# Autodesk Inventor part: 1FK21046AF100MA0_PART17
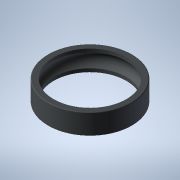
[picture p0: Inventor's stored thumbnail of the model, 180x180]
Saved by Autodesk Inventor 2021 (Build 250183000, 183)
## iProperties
Created: 2025-04
Part Number: 1FK21046AF100MA0_PART17
Material: Generic
Catalog Web Link: www.3dfindit.com
Description: -Servo synchronous motor
Document SubType Name: Modeling
Designer: psAdmin
Mass: 1.64389 g
Surface Area: 26.4305 cm^2
Volume: 1.64389 cm^3
Density: 1 g/cm^3
Appearance: PSOLRGB-212-217-219
Category: PARTsolutions
Title: 1FK21046AF100MA0_PART17
Author: Cadenas PARTsolutions
Comments: Servo synchronous motor
Sending System: PARTsolutions
Preprocessor: ST-DEVELOPER v19.3
PSOL_IDENT_0: {$CADENAS_DATA/23d-libs/siemens_ag/_cat_/4f/2b/1fk21046af100ma0.prj},216 {VTYP=3D},{NB=1FK21046AF100
PSOL_IDENT_1: MA0_PART17},{LINA=1FK21046AF100MA0_PART17},{NN=1FK21046AF100MA0_PART17},{NOPRJ=TRUE},{DATE=19.08.202
PSOL_IDENT_2: 5 14:00:37},{GEOMDATE=30.07.2025 02:01:06},{VERSION=},{LINEID=10},{WBVAR=},{WBNUMERIC=}  {NB=1FK2104
PSOL_IDENT_3: 6AF100MA0_PART17},{LINA=1FK21046AF100MA0_PART17},{KT=DUMMY},{PREVIEW=../../../_pool_/cb/72/p_d211_xx
PSOL_IDENT_4: _00434j.png},{DESCSHORT=SIMOTICS S-1FK2 HD, SINAMICS S210 3AC 400V-480V, 3.2 Nm, 3000 rpm},{DESCLONG=
PSOL_IDENT_5: SIMOTICS S-1FK2 HD servo motor M0=3.2 Nm; PN = 1 kW at nN=3000 rpm (380-480 V); PN = 0.5 kW at nN=15
PSOL_IDENT_6: 00 rpm (200-240 V); with holding brake; degree of protection IP64; cylindrical shaft D19x40mm; absol
PSOL_IDENT_7: ute encoder 22-bit + 12-bit multiturn (encoder AM22DQC); with OCC interface; plug size M17, rotatabl
PSOL_IDENT_8: e; SIMOTICS S-1FK2 servomotorfor a wide range of uses in industrial environments. SIMOTICS S‑1FK2 se
PSOL_IDENT_9: rvomotors are compact synchronous motors with a high dynamic performance that set themselves apart a
PSOL_IDENT_10: s a result of their high power density, degree of protection and overload capability. The motors are
PSOL_IDENT_11: available in two variants: as High Dynamic variant (highest dynamic performance as a result of the
PSOL_IDENT_12: low intrinsic moment of inertia for applications demanding a high dynamic performance with low moved
PSOL_IDENT_13: masses) - and as Compact variant (precise and stable closed-loop control for medium up to large mov
PSOL_IDENT_14: ed masses as a result of a medium intrinsic moment of inertia). SIMOTICSS‑1FK2 servomotors fully exp
PSOL_IDENT_15: loit their strengths in a system with the SINAMICSS210 frequency converter and simple connection usi
PSOL_IDENT_16: ng the one cable connection (OCC). Advantages include the short control and positioning times, fast
PSOL_IDENT_17: and precise correction of disturbing quantities as well as stable control with a high dynamic perfor
PSOL_IDENT_18: mance. The servo motors can be configured to address a wide range of requirements. For example with
PSOL_IDENT_19: and without holding brake, IP64 or IP65 degree of protection, singleturn or multiturn absolute encod
PSOL_IDENT_20: ers - to name just a few. Further, the servomotors are available in different shaft heights extendin
PSOL_IDENT_21: g from 20 to 100. A shaft sealing ring is available to achieve an IP65 degree of protection and for
PSOL_IDENT_22: subsequent mounting at the motor or as spare part. SIMOTICS - the optimum motor for each and every m
PSOL_IDENT_23: otion control application.},{INTNO=195125049673},{SUPPLIERALTNO=1FK2104-6AF10-0MA0},{MANUID=1FK21046
PSOL_IDENT_24: AF100MA0},{MANUNAME=Siemens},{MANUTYPEDESC=Synchronous motor 1FK2-HD 3.2 NM},{AAU732=SIMOTICS},{AAO0
PSOL_IDENT_25: 57=S-1FK2},{AAU734=SIMOTICS S-1FK2 HD servo motor M0=3.2 Nm; PN = 1 kW at nN=3000 rpm (380-480 V); P
PSOL_IDENT_26: N = 0.5 kW at nN=1500 rpm (200-240 V); with holding brake; degree of protection IP64; cylindrical sh
PSOL_IDENT_27: aft D19x40mm; absolute encoder 22-bit + 12-bit multiturn (encoder AM22DQC); with OCC interface; plug
PSOL_IDENT_28: size M17, rotatable;},{AAW338=Synchronous motor 1FK2-HD 3.2 NM},{AAO742=SIMOTICS},{AAO663=404294869
PSOL_IDENT_29: 4534},{NOCUPEROU=1},{PRICEQUANTITY=1},{QUANTITYMIN=1},{QUANTITYINT=1},{CTN=85015220},{COO=DE},{AAO67
PSOL_IDENT_30: 6=1FK2104-6AF10-0MA0},{AAO677=Siemens AG},{ORDERUNIT=C62},{CONTENTUNIT=C62}
NB: 1FK21046AF100MA0_PART17
NT: Servo synchronous motor
NBSYN: $MANUID._PART17
LINA: 1FK21046AF100MA0_PART17
CATALOG: SIEMENS
PREVIEW: ../../../_pool_/cb/72/p_d211_xx_00434j.png
DESCSHORT: SIMOTICS S-1FK2 HD, SINAMICS S210 3AC 400V-480V, 3.2 Nm, 3000 rpm
DESCLONG: SIMOTICS S-1FK2 HD servo motor M0=3.2 Nm; PN = 1 kW at nN=3000 rpm (380-480 V); PN = 0.5 kW at nN=1500 rpm (200-240 V); with holding brake; degree of protection
INTNO: 195125049673
SUPPLIERALTNO: 1FK2104-6AF10-0MA0
MANUID: 1FK21046AF100MA0
MANUNAME: Siemens
MANUTYPEDESC: Synchronous motor 1FK2-HD 3.2 NM
AAU732: SIMOTICS
AAO057: S-1FK2
AAU734: SIMOTICS S-1FK2 HD servo motor M0=3.2 Nm; PN = 1 kW at nN=3000 rpm (380-480 V); PN = 0.5 kW at nN=1500 rpm (200-240 V); with holding brake; degree of protection
AAW338: Synchronous motor 1FK2-HD 3.2 NM
AAO742: SIMOTICS
AAO663: 4042948694534.0
NOCUPEROU: 1
PRICEQUANTITY: 1
QUANTITYMIN: 1
QUANTITYINT: 1
CTN: 85015220
COO: DE
ARTICLENO: 1FK21046AF100MA0_PART17
BOMINFO: 1FK21046AF100MA0_PART17
CREATOR: CADENAS GmbH
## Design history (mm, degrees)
feature "2025_04_17_14_59_39_0177"
body "Solid1"
